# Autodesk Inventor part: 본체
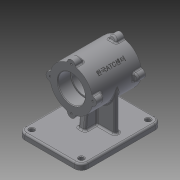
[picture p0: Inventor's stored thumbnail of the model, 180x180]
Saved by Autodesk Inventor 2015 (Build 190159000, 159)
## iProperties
Created: 2015-12
Part Number: 본체
Material: 일반
Document SubType Name: Modeling
Designer: Administrator
Density: 1 g/cm^3
Appearance: 기본값
Author: Administrator
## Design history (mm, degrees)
sketch "스케치1"
  geometry: L1 (-55, 60)-(55, 60); L2 (55, 60)-(55, -80); L3 (55, -80)-(-55, -80); L4 (-55, -80)-(-55, 60); 1 further point
  constraints: 8 end point, 2 parallel, 1 horizontal, 1 perpendicular
  dimensions: "d0" = 110 distance between parallel lines of L2 L4; "d1" = 140 distance between parallel lines of L3 L1; "d2" = 80 distance from line of L3 point (0, 0); "d3" = 55 distance from line of L4 point (0, 0)
extrude "돌출1" new body sketch "스케치1" distance "d4" = 10; taper "d5" = 0 deg
fillet "모깎기1" dims "d6" = 12
hole "구멍1" diameter "d10" = 8; stored, may be unused: countersink angle "d14" = 90 deg, drill point angle "d16" = 118 deg; dims "d8" = 10, "d9" = 10, "d11" = 6, "d12" = 4, "d13" = 2, "d15" = 8
hole "구멍2" diameter "d19" = 8; stored, may be unused: countersink angle "d23" = 90 deg, drill point angle "d25" = 118 deg; dims "d17" = 10, "d18" = 10, "d20" = 6, "d21" = 4, "d22" = 2, "d24" = 8
hole "구멍3" diameter "d28" = 8; stored, may be unused: countersink angle "d32" = 90 deg, drill point angle "d34" = 118 deg; dims "d26" = 10, "d27" = 10, "d29" = 6, "d30" = 4, "d31" = 2, "d33" = 8
hole "구멍4" diameter "d37" = 8; stored, may be unused: countersink angle "d41" = 90 deg, drill point angle "d43" = 118 deg; dims "d35" = 10, "d36" = 10, "d38" = 6, "d39" = 4, "d40" = 2, "d42" = 8
fillet "모깎기2" dims "d7" = 3
node "작업 평면1"
sketch "스케치2"
  geometry: L1 (0, 0)-(86, 0) reference; C1 r 37 at (43, 80); 1 further point
  constraints: 1 centre point
  dimensions: "d45" = 74 diameter of C1; "d46" = 80 distance from line of L1 C1.centre
extrude "돌출2" join sketch "스케치2" stored distance "d47" = 85; taper "d48" = 0 deg
sketch "스케치3"
  geometry: L1 (55, -73)-(55, -80) reference; L2 (55, -80)-(-55, -80) reference; L3 (-55, -80)-(-55, -73) reference; L4 (-52, -70)-(52, -70) reference; A1 r 3 centre (52, -73) between (55, -73) and (52, -70) reference; A2 r 3 centre (-52, -73) between (-52, -70) and (-55, -73) reference; A3 r 7 centre (0, 37) between (6.969, 36.338) and (-6.969, 36.338); A4 r 7 centre (-37, 0) between (-36.338, 6.969) and (-36.338, -6.969); A5 r 7 centre (0, -37) between (-6.969, -36.338) and (6.969, -36.338); A6 r 7 centre (37, 0) between (36.338, -6.969) and (36.338, 6.969); 2 further points
  constraints: 8 point on circle, 4 centre point, 10 other
  dimensions: "d49" = 14 diameter of A3
extrude "돌출3" join sketch "스케치3" distance "d53" = 15; taper "d54" = 0 deg
sketch "스케치4"
  geometry: L1 (-42.5, 124)-(-27.5, 124) reference; L2 (-27.5, 124)-(-27.5, 117) reference; L3 (-27.5, 117)-(42.5, 117) reference; L4 (42.5, 117)-(42.5, 43) reference; L5 (42.5, 43)-(-27.5, 43) reference; L6 (-27.5, 43)-(-27.5, 36) reference; L7 (-27.5, 36)-(-42.5, 36) reference; L8 (-42.5, 36)-(-42.5, 124) reference; L9 (60, 7)-(60, 0) reference; L10 (60, 0)-(-80, 0) reference; L11 (-80, 0)-(-80, 7) reference; L12 (-77, 10)-(57, 10) reference; L13 (-27.5, 117)-(-30.048, 124); L14 (-42.5, 80)-(42.5, 80); A1 r 3 centre (57, 7) between (60, 7) and (57, 10) reference; A2 r 3 centre (-77, 7) between (-77, 10) and (-80, 7) reference; 1 further point
  constraints: 4 end point, 2 midpoint, 1 point on line
  dimensions: "d55" = 110 deg angle of L3 L13; "d56" = 74 diameter of L3 L14 (derived)
revolve "회전1" sketch "스케치4" stored, may be unused: angle "d57" = 90 deg
hole "구멍5" diameter "d60" = 3.242; stored, may be unused: countersink angle "d64" = 90 deg, drill point angle "d66" = 118 deg; dims "d58" = 10, "d59" = 10, "d61" = 9, "d62" = 4, "d63" = 2, "d65" = 11
hole "구멍6" diameter "d69" = 3.242; stored, may be unused: countersink angle "d73" = 90 deg, drill point angle "d75" = 118 deg; dims "d67" = 10, "d68" = 10, "d70" = 9, "d71" = 4, "d72" = 2, "d74" = 11
hole "구멍7" diameter "d78" = 3.242; stored, may be unused: countersink angle "d82" = 90 deg, drill point angle "d84" = 118 deg; dims "d76" = 10, "d77" = 10, "d79" = 9, "d80" = 4, "d81" = 2, "d83" = 11
hole "구멍8" diameter "d87" = 3.242; stored, may be unused: countersink angle "d91" = 90 deg, drill point angle "d93" = 118 deg; dims "d85" = 10, "d86" = 10, "d88" = 9, "d89" = 4, "d90" = 2, "d92" = 11
hole "구멍9" diameter "d96" = 42; stored, may be unused: countersink angle "d100" = 90 deg, drill point angle "d102" = 0 deg; dims "d94" = 10, "d95" = 10, "d97" = 9, "d98" = 47, "d99" = 22, "d101" = 41
hole "구멍10" diameter "d105" = 47; stored, may be unused: countersink angle "d109" = 90 deg, drill point angle "d111" = 0 deg; dims "d103" = 10, "d104" = 10, "d106" = 9, "d107" = 4, "d108" = 2, "d110" = 22
fillet "모깎기3" dims "d112" = 0.3
chamfer "모따기1" distance "d113" = 1; stored, may be unused: second distance "d114" = 2, angle "d115" = 45 deg
chamfer "모따기2" distance "d116" = 1; stored, may be unused: second distance "d117" = 2, angle "d118" = 45 deg
sketch "스케치5"
  geometry: L1 (60, 7)-(60, 0) reference; L2 (60, 0)-(-80, 0) reference; L3 (-80, 0)-(-80, 7) reference; L4 (-77, 10)-(57, 10) reference; L5 (-27.5, 43)-(-30.048, 36) reference; L6 (-30.048, 36)-(-42.5, 36) reference; L7 (-42.5, 36)-(-42.5, 41.379) reference; L8 (-42.5, 41.379)-(-31.5, 41.379) reference; L9 (-31.5, 41.379)-(-30.526, 43) reference; L10 (-30.526, 43)-(-31.5, 44.621) reference; L11 (-31.5, 44.621)-(-42.5, 44.621) reference; L12 (-42.5, 44.621)-(-42.5, 55.5) reference; L13 (-42.5, 55.5)-(-41.5, 56.5) reference; L14 (-41.5, 56.5)-(-20.8, 56.5) reference; L15 (-20.5, 56.8)-(-20.5, 59) reference; L16 (-20.5, 59)-(20.5, 59) reference; L17 (20.5, 59)-(20.5, 56.8) reference; L18 (20.8, 56.5)-(41.5, 56.5) reference; L19 (41.5, 56.5)-(42.5, 55.5) reference; L20 (42.5, 55.5)-(42.5, 44.621) reference; L21 (42.5, 44.621)-(31.5, 44.621) reference; L22 (31.5, 44.621)-(30.526, 43) reference; L23 (30.526, 43)-(31.5, 41.379) reference; L24 (31.5, 41.379)-(42.5, 41.379) reference; L25 (42.5, 41.379)-(42.5, 36) reference; L26 (42.5, 36)-(30.048, 36) reference; L27 (30.048, 36)-(27.5, 43) reference; L28 (27.5, 43)-(-27.5, 43) reference; L29 (-30.048, 124)-(-27.5, 117) reference; L30 (-27.5, 117)-(27.5, 117) reference; L31 (27.5, 117)-(30.048, 124) reference; L32 (30.048, 124)-(42.5, 124) reference; L33 (42.5, 124)-(42.5, 118.621) reference; L34 (42.5, 118.621)-(31.5, 118.621) reference; L35 (31.5, 118.621)-(30.526, 117) reference; L36 (30.526, 117)-(31.5, 115.379) reference; L37 (31.5, 115.379)-(42.5, 115.379) reference; L38 (42.5, 115.379)-(42.5, 104.5) reference; L39 (42.5, 104.5)-(41.5, 103.5) reference; L40 (41.5, 103.5)-(20.8, 103.5) reference; L41 (20.5, 103.2)-(20.5, 101) reference; L42 (20.5, 101)-(-20.5, 101) reference; L43 (-20.5, 101)-(-20.5, 103.2) reference; L44 (-20.8, 103.5)-(-41.5, 103.5) reference; L45 (-41.5, 103.5)-(-42.5, 104.5) reference; L46 (-42.5, 104.5)-(-42.5, 115.379) reference; L47 (-42.5, 115.379)-(-31.5, 115.379) reference; L48 (-31.5, 115.379)-(-30.526, 117) reference; L49 (-30.526, 117)-(-31.5, 118.621) reference; L50 (-31.5, 118.621)-(-42.5, 118.621) reference; L51 (-42.5, 118.621)-(-42.5, 124) reference; L52 (-42.5, 124)-(-30.048, 124) reference; L53 (20.334, 48)-(25, 10); L54 (-20.334, 48)-(-25, 10); L55 (-20.334, 48)-(20.334, 48); A1 r 3 centre (57, 7) between (60, 7) and (57, 10) reference; A2 r 3 centre (-77, 7) between (-77, 10) and (-80, 7) reference; A3 r 0.3 centre (-20.8, 56.8) between (-20.8, 56.5) and (-20.5, 56.8) reference; A4 r 0.3 centre (20.8, 56.8) between (20.5, 56.8) and (20.8, 56.5) reference; A5 r 0.3 centre (20.8, 103.2) between (20.8, 103.5) and (20.5, 103.2) reference; A6 r 0.3 centre (-20.8, 103.2) between (-20.5, 103.2) and (-20.8, 103.5) reference; 1 further point
  constraints: 6 end point, 2 point on line, 1 horizontal
  dimensions: "d119" = 97 deg angle of L4 L53; "d120" = 97 deg angle of L4 L54; "d121" = 25 horizontal distance of L53.end point (0, 0); "d122" = 50 distance of L53.end L54.end (= 2 x d121); "d123" = 38 distance between parallel lines of L4 L55; "d124" = 42.5 distance from line of L20 point (0, 0) (derived)
feature "리브1" sketch "스케치5" dims "d125" = 1, "d126" = 12, "d127" = 0, "d128" = 0, "d129" = 1, "d130" = 1
sketch "리브스케치공유"
  geometry: L1 (-52, 10)-(-6, 10) reference; L2 (-6, 10)-(-6, 43.49) reference; L3 (6, 43.49)-(6, 10) reference; L4 (6, 10)-(52, 10) reference; L5 (55, 7)-(55, 0) reference; L6 (55, 0)-(-55, 0) reference; L7 (-55, 0)-(-55, 7) reference; L8 (-37, 80)-(-37, 10); L9 (37, 80)-(37, 10); C1 r 21 at (0, 80) reference; A1 r 3 centre (-52, 7) between (-52, 10) and (-55, 7) reference; A2 r 37 centre (0, 80) between (6, 43.49) and (-6, 43.49) reference; A3 r 3 centre (52, 7) between (55, 7) and (52, 10) reference; 1 further point
  constraints: 4 end point, 2 point on circle, 2 point on line, 2 tangent, 1 perpendicular, 1 vertical
  node "절단 모서리 투영4"
feature "리브2" dims "d131" = 1, "d132" = 8, "d133" = 0, "d134" = 0, "d135" = 1, "d136" = 1
feature "리브3" dims "d137" = 1, "d138" = 8, "d139" = 0, "d140" = 0, "d141" = 1, "d142" = 1
fillet "모깎기4" dims "d143" = 3
fillet "모깎기5" dims "d144" = 3
fillet "모깎기6" dims "d145" = 3
fillet "모깎기7" dims "d146" = 3
sketch "엠보싱기준"
  geometry: L1 (0, 80)-(-26.163, 106.163); L2 (0, 80)-(37, 80); 1 further point
  constraints: 4 end point, 1 equal length, 1 horizontal
  dimensions: "d147" = 37 distance of L1.start L1.end; "d148" = 135 deg angle of L2 L1
node "엠보싱작업평면"
sketch "스케치8"
  geometry: L1 (42.5, 37)-(-42.5, 37) reference; L2 (-42.5, 18.921)-(-42.5, -18.921) reference; 3 further points
  constraints: 1 coincident, 1 other
  dimensions: "d149" = 42.5 distance from line of point (0, 0) L2 (derived)
feature "엠보싱1" sketch "스케치8" dims "d10" = 8, "d12" = 4, "d13" = 2, "d15" = 8, "d150" = 0.5, "d151" = 0
chamfer "모따기3" distance "d152" = 1; stored, may be unused: second distance "d153" = 2, angle "d154" = 45 deg
node "솔리드1"
mirror "대칭1"
node "절단 모서리 투영1"
node "절단 모서리 투영2"
node "절단 모서리 투영3"
